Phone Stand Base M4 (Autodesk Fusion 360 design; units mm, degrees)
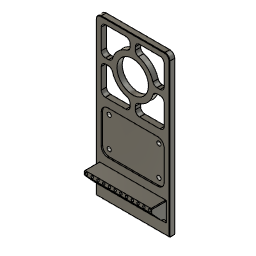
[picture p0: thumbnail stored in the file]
sketch "Sketch1" plane through (0, 0, 0) normal (0, 0, 1) x axis (1, 0, 0)
  line L1 (190.5, 0) -> (0, 0)
  line L2 (190.5, 88.9) -> (190.5, 0)
  line L3 (0, 88.9) -> (190.5, 88.9)
  line L4 (0, 0) -> (0, 88.9)
  point P1 (0, 0)
  point P2 (0, 0)
  point P3 (190.5, 0)
  point P5 (0, 88.9)
  horizontal L1
  vertical L2
  horizontal L3
  vertical L4
  coincident P1 P2
  dimension "d1" distance P2 P3 = 190.5
  dimension "d2" distance P2 P5 = 88.9
extrude "Extrude1" new body sketch "Sketch1" along normal blind 6.35
sketch "Sketch2" plane through (0, 0, 6.35) normal (0, 0, 1) x axis (-1, 0, 0)
  line L1 (0, 0) -> (0, -88.9)
  line L2 (-190.5, 0) -> (0, 0)
  line L3 (-190.5, -88.9) -> (-190.5, 0)
  line L4 (0, -88.9) -> (-190.5, -88.9)
  line L5 (-36.83, -85.09) -> (-19.05, -85.09)
  line L6 (-36.83, -3.81) -> (-36.83, -85.09)
  line L7 (-19.05, -3.81) -> (-36.83, -3.81)
  line L8 (-19.05, -85.09) -> (-19.05, -3.81)
  horizontal L5
  vertical L6
  horizontal L7
  vertical L8
  dimension "d5" distance L1 L8 = 19.05
  dimension "d6" distance L6 L8 = 17.78
  dimension "d7" distance L4 L5 = 3.81
  dimension "d8" distance L2 L7 = 3.81
extrude "Extrude2" add sketch "Sketch2" profile of L5 L6 L7 L8 along normal blind 17.78
fillet "Fillet1" radius 6
chamfer "Chamfer1" distance 12.7 distance 11.43
fillet "Fillet2" radius 6
chamfer "Chamfer2" distance 0.5 distance 0.508
fillet "Fillet4" radius 0.75
sketch "Sketch5" plane through (0, 0, 6.35) normal (0, 0, 1) x axis (-1, 0, 0)
  line L1 (-36.08, -85.09) -> (-13.05, -85.09)
  line L2 (-36.83, -4.56) -> (-36.83, -84.34)
  line L3 (-13.05, -3.81) -> (-36.08, -3.81)
  line L4 (-13.05, -85.09) -> (-13.05, -3.81)
  line L5 (-184.5, -0.5) -> (-0.5, -0.5)
  line L6 (-190, -82.9) -> (-190, -6)
  line L7 (-0.5, -88.4) -> (-184.5, -88.4)
  line L8 (-0.5, -0.5) -> (-0.5, -88.4)
  line L9 (0, -88.9) -> (-184.5, -88.9)
  line L10 (-190.5, -82.9) -> (-190.5, -6)
  line L11 (-184.15, -77.47) -> (-184.15, -52.705)
  line L12 (-154.305, -82.55) -> (-179.07, -82.55)
  line L13 (-184.15, -44.45) -> (-171.45, -44.45)
  line L14 (-190.5, -44.45) -> (-190, -44.45)
  line L15 (-179.07, -47.625) -> (-171.2508, -47.625)
  line L16 (-146.05, -82.55) -> (-146.05, -69.85)
  line L17 (-146.05, -88.9) -> (-146.05, -88.4)
  line L18 (-149.225, -77.47) -> (-149.225, -69.6508)
  line L19 (-149.225, -88.9) -> (-149.225, -88.4)
  arc A1 centre (-36.08, -84.34) radius 0.75 clockwise from (-36.08, -85.09) to (-36.83, -84.34)
  arc A2 centre (-36.08, -4.56) radius 0.75 clockwise from (-36.83, -4.56) to (-36.08, -3.81)
  arc A3 centre (-184.5, -6) radius 5.5 clockwise from (-190, -6) to (-184.5, -0.5)
  arc A4 centre (-184.5, -82.9) radius 5.5 clockwise from (-184.5, -88.4) to (-190, -82.9)
  circle C1 centre (-146.05, -44.45) radius 19.05
  circle C2 centre (-146.05, -44.45) radius 25.4
  arc A5 centre (-179.07, -77.47) radius 5.08 clockwise from (-179.07, -82.55) to (-184.15, -77.47)
  arc A6 centre (-154.305, -77.47) radius 5.08 clockwise from (-149.225, -77.47) to (-154.305, -82.55)
  arc A7 centre (-179.07, -52.705) radius 5.08 clockwise from (-184.15, -52.705) to (-179.07, -47.625)
  point P24 (-149.225, -69.6508)
  point P25 (-146.05, -69.85)
  point P26 (-171.2508, -47.625)
  point P27 (-171.45, -44.45)
  point P28 (-190.5, -44.45)
  point P29 (-184.15, -44.45)
  point P30 (-190, -44.45)
  point P31 (-146.05, -82.55)
  point P32 (-146.05, -88.4)
  point P33 (-149.225, -88.4)
  point P34 (-149.225, -88.9)
  point P35 (-146.05, -88.9)
  point P18 (-146.05, -44.45)
  coincident C2 P24
  coincident C2 P25
  coincident C2 P26
  coincident C2 P27
  coincident L10 P28
  coincident L11 P29
  coincident L6 P30
  collinear L13 L14
  coincident L12 P31
  coincident L7 P32
  collinear L16 L17
  coincident L7 P33
  collinear L18 L19
  coincident L9 P34
  coincident L9 P35
  tangent L12 A5
  tangent L11 A5
  tangent L18 A6
  tangent L12 A6
  tangent L11 A7
  tangent L15 A7
  dimension "d51" distance P18 L9 = 44.45
  dimension "d52" distance P18 L10 = 44.45
  dimension "d53" diameter C1 = 38.1
  dimension "d54" = 6.35
  dimension "d58" radius A5 = 5.08
  dimension "d59" radius A6 = 5.08
  dimension "d60" radius A7 = 5.08
extrude "Extrude5" cut sketch "Sketch5" profile of C1 C2 L19 L15 L11 L12 A5 A6 A7 no distance stored
fillet "Fillet5" radius 5
fillet "Fillet6" radius 5
circular_pattern "C-Pattern1" TotalAngle 360
fillet "Fillet7" radius 5
sketch "Sketch6" plane through (0, 0, 6.35) normal (0, 0, 1) x axis (-1, 0, 0)
  line L1 (-107.95, -77.47) -> (-107.95, -52.705)
  line L2 (-137.795, -82.55) -> (-113.03, -82.55)
  line L3 (-142.875, -73.7302) -> (-142.875, -77.47)
  line L4 (-113.03, -47.625) -> (-116.7698, -47.625)
  line L5 (-113.03, -6.35) -> (-137.795, -6.35)
  line L6 (-107.95, -36.195) -> (-107.95, -11.43)
  line L7 (-116.7698, -41.275) -> (-113.03, -41.275)
  line L8 (-142.875, -11.43) -> (-142.875, -15.1698)
  line L9 (-184.15, -11.43) -> (-184.15, -36.195)
  line L10 (-154.305, -6.35) -> (-179.07, -6.35)
  line L11 (-149.225, -15.1698) -> (-149.225, -11.43)
  line L12 (-179.07, -41.275) -> (-175.3302, -41.275)
  line L13 (-179.07, -82.55) -> (-154.305, -82.55)
  line L14 (-184.15, -52.705) -> (-184.15, -77.47)
  line L15 (-175.3302, -47.625) -> (-179.07, -47.625)
  line L16 (-149.225, -77.47) -> (-149.225, -73.7302)
  line L17 (-36.08, -85.09) -> (-13.05, -85.09)
  line L18 (-36.83, -4.56) -> (-36.83, -84.34)
  line L19 (-13.05, -3.81) -> (-36.08, -3.81)
  line L20 (-13.05, -85.09) -> (-13.05, -3.81)
  line L21 (-184.5, -0.5) -> (-0.5, -0.5)
  line L22 (-190, -82.9) -> (-190, -6)
  line L23 (-0.5, -88.4) -> (-184.5, -88.4)
  line L24 (-0.5, -0.5) -> (-0.5, -88.4)
  line L25 (-46.355, -82.55) -> (-98.425, -82.55)
  line L26 (-46.355, -6.35) -> (-46.355, -82.55)
  line L27 (-98.425, -6.35) -> (-46.355, -6.35)
  line L28 (-98.425, -82.55) -> (-98.425, -6.35)
  line L29 (0, -88.9) -> (-184.5, -88.9)
  arc A1 centre (-113.03, -52.705) radius 5.08 clockwise from (-113.03, -47.625) to (-107.95, -52.705)
  arc A2 centre (-113.03, -77.47) radius 5.08 clockwise from (-107.95, -77.47) to (-113.03, -82.55)
  arc A3 centre (-137.795, -77.47) radius 5.08 clockwise from (-137.795, -82.55) to (-142.875, -77.47)
  arc A4 centre (-137.875, -73.7302) radius 5 clockwise from (-142.875, -73.7302) to (-139.2196, -68.9144)
  arc A5 centre (-146.05, -44.45) radius 25.4 clockwise from (-121.5856, -51.2804) to (-139.2196, -68.9144)
  arc A6 centre (-116.7698, -52.625) radius 5 clockwise from (-121.5856, -51.2804) to (-116.7698, -47.625)
  arc A7 centre (-137.795, -11.43) radius 5.08 clockwise from (-142.875, -11.43) to (-137.795, -6.35)
  arc A8 centre (-113.03, -11.43) radius 5.08 clockwise from (-113.03, -6.35) to (-107.95, -11.43)
  arc A9 centre (-113.03, -36.195) radius 5.08 clockwise from (-107.95, -36.195) to (-113.03, -41.275)
  arc A10 centre (-116.7698, -36.275) radius 5 clockwise from (-116.7698, -41.275) to (-121.5856, -37.6196)
  arc A11 centre (-146.05, -44.45) radius 25.4 clockwise from (-139.2196, -19.9856) to (-121.5856, -37.6196)
  arc A12 centre (-137.875, -15.1698) radius 5 clockwise from (-139.2196, -19.9856) to (-142.875, -15.1698)
  arc A13 centre (-179.07, -36.195) radius 5.08 clockwise from (-179.07, -41.275) to (-184.15, -36.195)
  arc A14 centre (-179.07, -11.43) radius 5.08 clockwise from (-184.15, -11.43) to (-179.07, -6.35)
  arc A15 centre (-154.305, -11.43) radius 5.08 clockwise from (-154.305, -6.35) to (-149.225, -11.43)
  arc A16 centre (-154.225, -15.1698) radius 5 clockwise from (-149.225, -15.1698) to (-152.8804, -19.9856)
  arc A17 centre (-146.05, -44.45) radius 25.4 clockwise from (-170.5144, -37.6196) to (-152.8804, -19.9856)
  arc A18 centre (-175.3302, -36.275) radius 5 clockwise from (-170.5144, -37.6196) to (-175.3302, -41.275)
  arc A19 centre (-154.305, -77.47) radius 5.08 clockwise from (-149.225, -77.47) to (-154.305, -82.55)
  arc A20 centre (-179.07, -77.47) radius 5.08 clockwise from (-179.07, -82.55) to (-184.15, -77.47)
  arc A21 centre (-179.07, -52.705) radius 5.08 clockwise from (-184.15, -52.705) to (-179.07, -47.625)
  arc A22 centre (-175.3302, -52.625) radius 5 clockwise from (-175.3302, -47.625) to (-170.5144, -51.2804)
  arc A23 centre (-146.05, -44.45) radius 25.4 clockwise from (-152.8804, -68.9144) to (-170.5144, -51.2804)
  arc A24 centre (-154.225, -73.7302) radius 5 clockwise from (-152.8804, -68.9144) to (-149.225, -73.7302)
  circle C1 centre (-146.05, -44.45) radius 19.05
  arc A25 centre (-36.08, -84.34) radius 0.75 clockwise from (-36.08, -85.09) to (-36.83, -84.34)
  arc A26 centre (-36.08, -4.56) radius 0.75 clockwise from (-36.83, -4.56) to (-36.08, -3.81)
  arc A27 centre (-184.5, -6) radius 5.5 clockwise from (-190, -6) to (-184.5, -0.5)
  arc A28 centre (-184.5, -82.9) radius 5.5 clockwise from (-184.5, -88.4) to (-190, -82.9)
  horizontal L25
  vertical L26
  horizontal L27
  vertical L28
  dimension "d70" distance L25 L29 = 6.35
  dimension "d71" distance L25 L27 = 76.2
  dimension "d72" distance L6 L28 = 9.525
  dimension "d73" distance L18 L26 = 9.525
extrude "Extrude6" cut sketch "Sketch6" profile of L25 L26 L27 L28 against normal blind 1.6
fillet "Fillet8" radius 8
hole "Hole2" HoleDiameter 5.035 TipAngle 118
hole "Hole3" HoleDiameter 5.035 TipAngle 118
hole "Hole4" HoleDiameter 5.035 TipAngle 118
hole "Hole5" HoleDepth 30.48 HoleDiameter 5.035 TipAngle 118
hole "Hole6" HoleDepth 24.13 HoleDiameter 3 TipAngle 118 RefDim1 2.54 RefDim2 6.35
rectangular_pattern "R-Pattern2" countU 12 uSpaceDistance 76.2 vSpaceDistance 0
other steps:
thread "Thread2"
thread "Thread3"
thread "Thread4"
thread "Thread5"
